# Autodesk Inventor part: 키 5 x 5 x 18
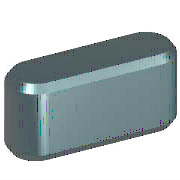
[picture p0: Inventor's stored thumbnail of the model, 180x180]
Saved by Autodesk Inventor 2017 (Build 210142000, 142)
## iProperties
IsCustomPart: 1
Created: 2012-02
Part Number: 키 5 x 5 x 18
Material: 강철, 연강
Description: 키 및 해당 키홈
Document SubType Name: Modeling
Standard: KS B 1311
Designer: mduedu
Standards Organization: KS
Language: ko-KR
Size Designation: 5 x 5 x 18
Categories: <MemberInstance><Categories><Category DisplayName="샤프트 부품" InternalName="7f7aeb1f-a693-4053-b835-cee3144e0d98" Mnemonic="SHFT"><Category DisplayName="키" Interna
Density: 1 g/cm^3
Appearance: 노란색
Author: mduedu
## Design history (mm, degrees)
workplane "Work Plane1"
workplane "Work Plane2"
sketch "스케치1"
  geometry: L1 (2.5, 2.5)-(15.5, 2.5); L2 (15.5, -2.5)-(2.5, -2.5); L3 (0, 9.4)-(0, -7.4) reference; L4 (-5, 0)-(30, 0) reference; L5 (18, 0)-(18, 7); A1 r 2.5 centre (2.5, 0) between (2.5, 2.5) and (2.5, -2.5); A2 r 2.5 centre (15.5, 0) between (15.5, -2.5) and (15.5, 2.5)
  constraints: 6 end point, 5 point on circle, 4 tangent, 3 point on line, 2 centre point, 1 horizontal, 1 parallel, 1 perpendicular
  dimensions: "d0" = 2.5 radius of A1 (= 0.5 x PB); "d13" = 2.5 radius of A2 (= 0.5 x PB); "d14" = 18 distance between parallel lines of L5 L3 (= NLG)
extrude "본체1" new body sketch "스케치1" taper "d3" = 0 deg; stored distance "d4" = 10
workplane "Work Plane3"
body "Solid1"
chamfer "모따기1" distance "d8" = 0.4 (= PHH); stored, may be unused: second distance "d9" = 0.4 (= PHH), angle "d15" = 45 deg
other parameters: "d1" = -3 (= -PNT), "d2" = 2 (= PH - PNT), "NLG" = 18 [user parameter; used in 3 equation terms], "PB" = 5 [user parameter; used in 2 equation terms], "PNT" = 3 [user parameter; used in 2 equation terms], "PH" = 5 [user parameter; used in 1 equation term], "PHH" = 0.4 [user parameter; used in 2 equation terms], "d10" = 0, "d16" = 0, "d17" = 0, "d18" = 0, "WDMIN" = 12 [user parameter], "PLB2" = 18 (= NLG) [user parameter], "WDMAX" = 17 [user parameter], "PLB1" = 18 (= NLG) [user parameter], "RR" = 0.16 [user parameter], "PUEB" = 2.3 [user parameter]
